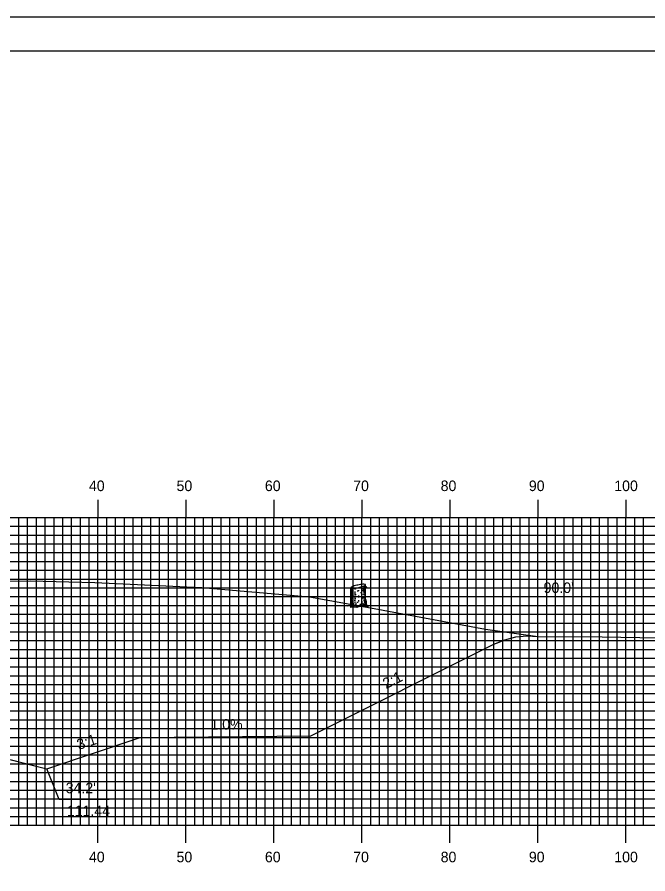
# Model space of a CAD drawing. Extents: x 1767694 to 1768037, y 442591 to 442811.
# Drawn here: x 1767890.3 to 1767961.9, y 442713.1 to 442810.5 of the extents above; entities that cross this region are included whole.
import ezdxf

# ---------------------------------------------------------------- set-up
doc = ezdxf.new("R2010")
doc.units = 0
for name, color, linetype in [('ANNOTATION', 7, 'Continuous'), ('BORDER', 7, 'Continuous'), ('D_Roadway_Centerline', 7, 'Continuous'), ('D_Roadway_SlopeLines', 7, 'Continuous'), ('D_Text_Standard', 7, 'Continuous'), ('H_V ANNOTATION', 7, 'Continuous'), ('M_Trees_Conifer_Pay', 7, 'Continuous'), ('MAJOR', 7, 'Continuous'), ('MINOR', 7, 'Continuous'), ('PLOT BOUNDARY', 7, 'Continuous'), ('S_Roadway_Centerline', 7, 'Continuous')]:
    doc.layers.add(name, color=color, linetype=linetype)

msp = doc.modelspace()

# ---------------------------------------------------------------- linework, layer by layer
at = {"layer": 'ANNOTATION'}
msp.add_lwpolyline([(1767900.736, 442721.591), (1767895.044, 442721.591), (1767893.624, 442725.102)], dxfattribs=at)
at = {"layer": 'BORDER'}
msp.add_lwpolyline([(1767709.85, 442596.665), (1768029.85, 442596.665), (1768029.85, 442806.665), (1767709.85, 442806.665)], close=True, dxfattribs=at)
at = {"layer": 'D_Roadway_Centerline'}
msp.add_lwpolyline([(1767889.623, 442726.102), (1767891.113, 442725.73), (1767893.624, 442725.102), (1767904.248, 442728.644), (1767904.254, 442728.646), (1767904.265, 442728.646), (1767923.635, 442728.839), (1767923.637, 442728.84), (1767944.45, 442739.247), (1767944.845, 442739.413), (1767945.7, 442739.772), (1767946.949, 442740.098), (1767948.2, 442740.223), (1767949.168, 442740.167), (1767949.45, 442740.15)], dxfattribs=at)
at = {"layer": 'D_Roadway_SlopeLines'}
for points in [[(1767904.254, 442728.646), (1767923.635, 442728.839), (1767944.45, 442739.247), (1767945.7, 442739.772), (1767946.949, 442740.098), (1767948.199, 442740.223), (1767949.449, 442740.15)], [(1767879.45, 442728.646), (1767893.624, 442725.102)], [(1767893.624, 442725.102), (1767904.254, 442728.646)]]:
    msp.add_lwpolyline(points, dxfattribs=at)
at = {"layer": 'M_Trees_Conifer_Pay'}
for p, q in [((1767928.198, 442743.956), (1767928.198, 442745.678)), ((1767928.245, 442745.641), (1767928.245, 442745.169)), ((1767928.303, 442745.629), (1767928.303, 442745.532)), ((1767928.303, 442745.457), (1767928.303, 442745.253)), ((1767928.303, 442745.196), (1767928.303, 442744.996)), ((1767928.429, 442745.622), (1767928.429, 442745.389)), ((1767928.429, 442745.349), (1767928.429, 442745.274)), ((1767928.649, 442745.642), (1767928.649, 442745.474)), ((1767928.649, 442745.237), (1767928.649, 442745)), ((1767929.054, 442745.41), (1767929.054, 442745.315)), ((1767929.445, 442745.684), (1767929.445, 442745.484)), ((1767929.445, 442745.427), (1767929.445, 442745.338)), ((1767929.673, 442745.88), (1767929.673, 442745.657)), ((1767929.673, 442745.568), (1767929.673, 442745.521)), ((1767929.673, 442745.186), (1767929.673, 442745.054)), ((1767929.73, 442745.385), (1767929.679, 442745.326)), ((1767929.79, 442745.941), (1767929.79, 442745.778)), ((1767929.79, 442745.711), (1767929.79, 442745.583)), ((1767929.79, 442745.396), (1767929.79, 442745.06)), ((1767929.862, 442744.366), (1767929.862, 442746.013)), ((1767928.245, 442745.105), (1767928.245, 442744.797)), ((1767928.245, 442744.749), (1767928.245, 442744.257)), ((1767928.245, 442744.204), (1767928.245, 442743.956)), ((1767928.303, 442744.949), (1767928.303, 442744.613)), ((1767928.303, 442744.56), (1767928.303, 442744.424)), ((1767928.303, 442744.325), (1767928.303, 442743.946)), ((1767928.429, 442744.871), (1767928.429, 442744.732)), ((1767928.429, 442744.461), (1767928.429, 442744.319)), ((1767928.649, 442744.755), (1767928.649, 442744.603)), ((1767928.649, 442744.56), (1767928.649, 442744.387)), ((1767929.054, 442744.797), (1767929.054, 442744.723)), ((1767929.054, 442744.698), (1767929.054, 442744.549)), ((1767929.054, 442744.257), (1767929.054, 442744.104)), ((1767929.445, 442744.99), (1767929.445, 442744.885)), ((1767929.445, 442744.518), (1767929.445, 442744.372)), ((1767929.673, 442744.943), (1767929.673, 442744.833)), ((1767929.673, 442744.698), (1767929.673, 442744.556)), ((1767929.673, 442744.329), (1767929.673, 442744.156)), ((1767929.79, 442745.023), (1767929.79, 442744.86)), ((1767929.79, 442744.813), (1767929.79, 442744.597)), ((1767929.79, 442744.566), (1767929.79, 442744.492)), ((1767929.79, 442744.451), (1767929.79, 442744.278)), ((1767928.429, 442744.057), (1767928.429, 442743.963)), ((1767928.429, 442743.563), (1767928.592, 442743.627)), ((1767928.649, 442744.109), (1767928.649, 442743.956)), ((1767928.866, 442743.499), (1767928.74, 442743.563)), ((1767929.445, 442744.14), (1767929.445, 442744.051))]:
    msp.add_line(p, q, dxfattribs=at)
for points in [[(1767929.645, 442745.474), (1767929.615, 442745.389), (1767929.611, 442745.322), (1767929.641, 442745.258)], [(1767929.679, 442745.511), (1767929.716, 442745.437), (1767929.763, 442745.494), (1767929.821, 442745.562), (1767929.913, 442745.756), (1767929.977, 442745.803), (1767930.008, 442745.81)], [(1767929.693, 442745.258), (1767929.73, 442745.385), (1767929.794, 442745.501), (1767929.824, 442745.568), (1767929.893, 442745.715)], [(1767929.908, 442745.744), (1767929.983, 442745.752), (1767930.055, 442745.653)], [(1767929.862, 442744.366), (1767929.913, 442744.104), (1767929.929, 442743.831), (1767929.987, 442743.705), (1767930.123, 442743.675), (1767929.893, 442743.637), (1767929.893, 442743.637), (1767929.899, 442743.59), (1767930.146, 442743.496), (1767929.872, 442743.512), (1767929.516, 442743.532), (1767929.195, 442743.522), (1767929.201, 442743.604), (1767929.053, 442743.522), (1767928.866, 442743.499), (1767928.89, 442743.431), (1767928.622, 442743.475), (1767928.402, 442743.448), (1767928.109, 442743.465), (1767928.398, 442743.522), (1767928.429, 442743.563), (1767928.266, 442743.621), (1767928.029, 442743.631), (1767927.788, 442743.631), (1767928.13, 442743.689), (1767928.172, 442743.769), (1767928.198, 442743.956)], [(1767928.377, 442744.984), (1767928.371, 442745.079), (1767928.414, 442745.056), (1767928.414, 442744.961)], [(1767929.516, 442744.585), (1767929.529, 442744.508), (1767929.576, 442744.518), (1767929.563, 442744.685)], [(1767929.788, 442744.224), (1767929.794, 442744.078), (1767929.841, 442744.01), (1767929.851, 442743.81)], [(1767928.246, 442743.909), (1767928.225, 442743.831), (1767928.204, 442743.736)], [(1767928.324, 442743.889), (1767928.33, 442743.773), (1767928.277, 442743.684), (1767928.266, 442743.621)], [(1767928.487, 442743.915), (1767928.487, 442743.784), (1767928.398, 442743.684)], [(1767928.713, 442743.675), (1767928.781, 442743.769), (1767928.807, 442743.909)], [(1767929.201, 442743.604), (1767929.275, 442743.746), (1767929.285, 442743.847)], [(1767929.452, 442743.973), (1767929.462, 442743.847), (1767929.536, 442743.804)], [(1767929.73, 442743.584), (1767929.716, 442743.722), (1767929.641, 442743.851)], [(1767929.689, 442744.078), (1767929.763, 442743.973), (1767929.767, 442743.8), (1767929.893, 442743.637)]]:
    msp.add_lwpolyline(points, dxfattribs=at)
for centre, radius, start, end in [((1767928.23, 442745.5), 0.0334, 163.94846, 180), ((1767928.23, 442745.5), 0.0334, 180, 196.05154), ((1767928.229, 442745.677), 0.0314, 156.51582, 169.2194), ((1767928.224, 442745.678), 0.0264, 169.2194, 180.03145), ((1767928.221, 442745.678), 0.0226, 180.03145, 191.7194), ((1767928.221, 442745.678), 0.0226, 191.7194, 203.40735), ((1767928.24, 442745.503), 0.0441, 196.05154, 210), ((1767928.249, 442745.668), 0.0527, 146.7194, 156.51582), ((1767928.224, 442745.679), 0.0264, 203.40735, 214.2194), ((1767928.228, 442745.682), 0.0314, 214.2194, 226.92298), ((1767928.256, 442745.512), 0.0624, 210, 228.74941), ((1767928.273, 442745.652), 0.0817, 132.38868, 146.7194), ((1767928.243, 442745.698), 0.0527, 226.92298, 236.7194), ((1767928.259, 442745.722), 0.0817, 236.7194, 251.05013), ((1767928.329, 442745.594), 0.172, 228.74941, 240), ((1767928.387, 442745.528), 0.251, 124.2194, 132.38868), ((1767928.314, 442745.881), 0.251, 251.05013, 259.2194), ((1767928.528, 442745.939), 0.571, 240, 240.33672), ((1767928.529, 442745.728), 0.571, 240, 247.05866), ((1767928.697, 442745.072), 0.802, 108.05939, 124.2194), ((1767928.417, 442746.423), 0.802, 259.2194, 275.37941), ((1767928.528, 442745.939), 0.571, 246.85973, 257.98457), ((1767930.054, 442740.91), 5.179, 101.7194, 108.05939), ((1767928.006, 442750.781), 5.179, 275.37941, 281.7194), ((1767929.03, 442749.69), 4.124, 264.6955, 266.73309), ((1767929.029, 442749.457), 4.124, 268.07512, 270), ((1767930.054, 442740.91), 5.179, 95.37941, 101.7194), ((1767929.029, 442749.457), 4.124, 270, 270.35814), ((1767928.006, 442750.781), 5.179, 281.7194, 288.05939), ((1767929.029, 442749.457), 4.124, 275.78493, 277.05584), ((1767929.03, 442749.69), 4.124, 276.23804, 278.1032), ((1767929.643, 442745.268), 0.802, 79.2194, 95.37941), ((1767929.531, 442746.172), 0.571, 278.1032, 284.36665), ((1767929.363, 442746.619), 0.802, 288.05939, 304.2194), ((1767929.531, 442746.327), 0.571, 284.43166, 292.41325), ((1767929.531, 442745.728), 0.571, 284.44928, 297.04285), ((1767929.531, 442746.172), 0.571, 297.0237, 300), ((1767929.746, 442745.81), 0.251, 71.05013, 79.2194), ((1767929.673, 442746.163), 0.251, 304.2194, 312.38868), ((1767929.73, 442745.982), 0.172, 300, 311.25059), ((1767929.73, 442745.827), 0.172, 300, 311.25059), ((1767929.801, 442745.969), 0.0817, 56.7194, 71.05013), ((1767929.787, 442746.039), 0.0817, 312.38868, 326.7194), ((1767929.803, 442745.899), 0.0624, 311.25059, 330), ((1767929.803, 442745.745), 0.0624, 311.25059, 330), ((1767929.817, 442745.994), 0.0527, 46.92298, 56.7194), ((1767929.832, 442746.009), 0.0314, 34.2194, 46.92298), ((1767929.811, 442746.023), 0.0527, 326.7194, 336.51582), ((1767929.818, 442745.89), 0.0441, 330, 343.94846), ((1767929.818, 442745.736), 0.0441, 330, 343.94846), ((1767929.836, 442746.012), 0.0264, 23.40735, 34.2194), ((1767929.831, 442746.014), 0.0314, 336.51582, 349.2194), ((1767929.839, 442746.013), 0.0226, 11.7194, 23.40735), ((1767929.829, 442745.887), 0.0334, 343.94846, 354.21506), ((1767929.829, 442745.733), 0.0334, 343.94846, 354.21506), ((1767929.829, 442745.289), 0.0334, 343.94846, 354.21506), ((1767929.839, 442746.013), 0.0226, 0.03145, 11.7194), ((1767929.836, 442746.013), 0.0264, 349.2194, 0.03145), ((1767928.23, 442745.053), 0.0334, 163.94846, 180), ((1767928.23, 442745.053), 0.0334, 180, 196.05154), ((1767928.23, 442744.843), 0.0334, 163.94846, 180), ((1767928.23, 442744.843), 0.0334, 180, 196.05154), ((1767928.23, 442744.606), 0.0334, 163.94846, 180), ((1767928.23, 442744.606), 0.0334, 180, 196.05154), ((1767928.23, 442744.408), 0.0334, 163.94846, 180), ((1767928.23, 442744.213), 0.0334, 163.94846, 180), ((1767928.23, 442744.213), 0.0334, 180, 196.05154), ((1767928.24, 442745.056), 0.0441, 196.05154, 210), ((1767928.24, 442744.846), 0.0441, 196.05154, 210), ((1767928.24, 442744.609), 0.0441, 196.05154, 210), ((1767928.24, 442744.216), 0.0441, 196.05154, 210), ((1767928.256, 442745.065), 0.0624, 210, 228.74941), ((1767928.256, 442744.855), 0.0624, 210, 228.74941), ((1767928.256, 442744.618), 0.0624, 210, 228.74941), ((1767928.256, 442744.225), 0.0624, 210, 228.74941), ((1767928.329, 442745.148), 0.172, 228.74941, 240), ((1767928.329, 442744.938), 0.172, 228.74941, 240), ((1767928.329, 442744.701), 0.172, 228.74941, 240), ((1767928.528, 442745.493), 0.571, 240, 240.33672), ((1767928.528, 442745.283), 0.571, 240, 246.85973), ((1767928.528, 442745.046), 0.571, 240, 246.85973), ((1767928.517, 442744.854), 0.571, 241.23686, 248.02677), ((1767928.528, 442745.283), 0.571, 259.27072, 261.8968), ((1767929.029, 442748.8), 4.124, 261.8968, 263.14738), ((1767929.029, 442748.366), 4.124, 263.49906, 265.83975), ((1767929.029, 442749.01), 4.124, 264.08098, 266.66759), ((1767929.029, 442748.563), 4.124, 264.71603, 266.31934), ((1767929.029, 442748.8), 4.124, 270, 270.35814), ((1767929.029, 442748.8), 4.124, 273.14934, 275.45691), ((1767929.03, 442749.246), 4.124, 273.70524, 275.95043), ((1767929.029, 442749.01), 4.124, 277.61247, 278.1032), ((1767929.529, 442745.493), 0.571, 278.1032, 286.92962), ((1767929.529, 442745.046), 0.571, 285.39827, 297.18959), ((1767929.529, 442744.848), 0.571, 289.29072, 300), ((1767929.529, 442745.493), 0.571, 297.18959, 300), ((1767929.529, 442745.283), 0.571, 297.18959, 300), ((1767929.729, 442745.148), 0.172, 300, 311.25059), ((1767929.729, 442744.938), 0.172, 300, 311.25059), ((1767929.729, 442744.503), 0.172, 300, 311.25059), ((1767929.801, 442745.065), 0.0624, 311.25059, 330), ((1767929.801, 442744.855), 0.0624, 311.25059, 330), ((1767929.801, 442744.421), 0.0624, 311.25059, 330), ((1767929.817, 442745.056), 0.0441, 330, 343.94846), ((1767929.817, 442744.846), 0.0441, 330, 343.94846), ((1767929.817, 442744.411), 0.0441, 330, 343.94846), ((1767929.827, 442745.053), 0.0334, 343.94846, 354.21506), ((1767929.827, 442744.843), 0.0334, 343.94846, 354.21506), ((1767929.827, 442744.408), 0.0334, 343.94846, 354.21506), ((1767928.23, 442743.993), 0.0334, 163.94846, 180), ((1767928.23, 442743.993), 0.0334, 180, 196.05154), ((1767928.24, 442743.995), 0.0441, 196.05154, 210), ((1767928.256, 442744.005), 0.0624, 210, 228.74941), ((1767928.329, 442744.308), 0.172, 228.74941, 240), ((1767928.329, 442744.087), 0.172, 228.74941, 240), ((1767928.528, 442744.653), 0.571, 240, 246.85973), ((1767928.528, 442744.432), 0.571, 240, 244.53138), ((1767929.029, 442747.95), 4.124, 262.44379, 263.51202), ((1767929.029, 442748.17), 4.124, 267.81166, 270), ((1767929.029, 442748.17), 4.124, 270, 270.13279), ((1767929.029, 442748.17), 4.124, 275.78493, 276.78961), ((1767929.029, 442747.95), 4.124, 277.36842, 278.1032), ((1767929.529, 442744.432), 0.571, 278.1032, 281.63703), ((1767929.529, 442744.653), 0.571, 288.50673, 297.27208), ((1767929.729, 442744.087), 0.172, 300, 311.25059), ((1767929.801, 442744.005), 0.0624, 311.25059, 330), ((1767929.817, 442743.995), 0.0441, 330, 343.94846), ((1767929.827, 442743.993), 0.0334, 343.94846, 354.21506)]:
    msp.add_arc(centre, radius, start, end, dxfattribs=at)
at = {"layer": 'MAJOR'}
for p, q in [((1767899.45, 442755.669), (1767899.45, 442753.665)), ((1767909.45, 442755.669), (1767909.45, 442753.665)), ((1767919.45, 442755.669), (1767919.45, 442753.665)), ((1767929.45, 442755.669), (1767929.45, 442753.665)), ((1767939.45, 442755.669), (1767939.45, 442753.665)), ((1767949.45, 442755.669), (1767949.45, 442753.665)), ((1767959.45, 442755.669), (1767959.45, 442753.665)), ((1767719.45, 442753.665), (1767999.45, 442753.665)), ((1767719.45, 442753.665), (1767999.45, 442753.665)), ((1767899.45, 442718.665), (1767899.45, 442753.665)), ((1767909.45, 442718.665), (1767909.45, 442753.665)), ((1767919.45, 442718.665), (1767919.45, 442753.665)), ((1767929.45, 442718.665), (1767929.45, 442753.665)), ((1767939.45, 442718.665), (1767939.45, 442753.665)), ((1767949.45, 442718.665), (1767949.45, 442753.665)), ((1767959.45, 442718.665), (1767959.45, 442753.665)), ((1767719.45, 442748.665), (1767999.45, 442748.665)), ((1767719.45, 442743.665), (1767999.45, 442743.665)), ((1767719.45, 442738.665), (1767999.45, 442738.665)), ((1767719.45, 442733.665), (1767999.45, 442733.665)), ((1767719.45, 442728.665), (1767999.45, 442728.665)), ((1767719.45, 442723.665), (1767999.45, 442723.665)), ((1767719.45, 442718.665), (1767999.45, 442718.665)), ((1767719.45, 442718.665), (1767999.45, 442718.665)), ((1767899.45, 442716.661), (1767899.45, 442718.665)), ((1767909.45, 442716.661), (1767909.45, 442718.665)), ((1767919.45, 442716.661), (1767919.45, 442718.665)), ((1767929.45, 442716.661), (1767929.45, 442718.665)), ((1767939.45, 442716.661), (1767939.45, 442718.665)), ((1767949.45, 442716.661), (1767949.45, 442718.665)), ((1767959.45, 442716.661), (1767959.45, 442718.665))]:
    msp.add_line(p, q, dxfattribs=at)
at = {"layer": 'MINOR'}
for p, q in [((1767890.45, 442718.665), (1767890.45, 442753.665)), ((1767891.45, 442718.665), (1767891.45, 442753.665)), ((1767892.45, 442718.665), (1767892.45, 442753.665)), ((1767893.45, 442718.665), (1767893.45, 442753.665)), ((1767894.45, 442718.665), (1767894.45, 442753.665)), ((1767895.45, 442718.665), (1767895.45, 442753.665)), ((1767896.45, 442718.665), (1767896.45, 442753.665)), ((1767897.45, 442718.665), (1767897.45, 442753.665)), ((1767898.45, 442718.665), (1767898.45, 442753.665)), ((1767900.45, 442718.665), (1767900.45, 442753.665)), ((1767901.45, 442718.665), (1767901.45, 442753.665)), ((1767902.45, 442718.665), (1767902.45, 442753.665)), ((1767903.45, 442718.665), (1767903.45, 442753.665)), ((1767904.45, 442718.665), (1767904.45, 442753.665)), ((1767905.45, 442718.665), (1767905.45, 442753.665)), ((1767906.45, 442718.665), (1767906.45, 442753.665)), ((1767907.45, 442718.665), (1767907.45, 442753.665)), ((1767908.45, 442718.665), (1767908.45, 442753.665)), ((1767910.45, 442718.665), (1767910.45, 442753.665)), ((1767911.45, 442718.665), (1767911.45, 442753.665)), ((1767912.45, 442718.665), (1767912.45, 442753.665)), ((1767913.45, 442718.665), (1767913.45, 442753.665)), ((1767914.45, 442718.665), (1767914.45, 442753.665)), ((1767915.45, 442718.665), (1767915.45, 442753.665)), ((1767916.45, 442718.665), (1767916.45, 442753.665)), ((1767917.45, 442718.665), (1767917.45, 442753.665)), ((1767918.45, 442718.665), (1767918.45, 442753.665)), ((1767920.45, 442718.665), (1767920.45, 442753.665)), ((1767921.45, 442718.665), (1767921.45, 442753.665)), ((1767922.45, 442718.665), (1767922.45, 442753.665)), ((1767923.45, 442718.665), (1767923.45, 442753.665)), ((1767924.45, 442718.665), (1767924.45, 442753.665)), ((1767925.45, 442718.665), (1767925.45, 442753.665)), ((1767926.45, 442718.665), (1767926.45, 442753.665)), ((1767927.45, 442718.665), (1767927.45, 442753.665)), ((1767928.45, 442718.665), (1767928.45, 442753.665)), ((1767930.45, 442718.665), (1767930.45, 442753.665)), ((1767931.45, 442718.665), (1767931.45, 442753.665)), ((1767932.45, 442718.665), (1767932.45, 442753.665)), ((1767933.45, 442718.665), (1767933.45, 442753.665)), ((1767934.45, 442718.665), (1767934.45, 442753.665)), ((1767935.45, 442718.665), (1767935.45, 442753.665)), ((1767936.45, 442718.665), (1767936.45, 442753.665)), ((1767937.45, 442718.665), (1767937.45, 442753.665)), ((1767938.45, 442718.665), (1767938.45, 442753.665)), ((1767940.45, 442718.665), (1767940.45, 442753.665)), ((1767941.45, 442718.665), (1767941.45, 442753.665)), ((1767942.45, 442718.665), (1767942.45, 442753.665)), ((1767943.45, 442718.665), (1767943.45, 442753.665)), ((1767944.45, 442718.665), (1767944.45, 442753.665)), ((1767945.45, 442718.665), (1767945.45, 442753.665)), ((1767946.45, 442718.665), (1767946.45, 442753.665)), ((1767947.45, 442718.665), (1767947.45, 442753.665)), ((1767948.45, 442718.665), (1767948.45, 442753.665)), ((1767950.45, 442718.665), (1767950.45, 442753.665)), ((1767951.45, 442718.665), (1767951.45, 442753.665)), ((1767952.45, 442718.665), (1767952.45, 442753.665)), ((1767953.45, 442718.665), (1767953.45, 442753.665)), ((1767954.45, 442718.665), (1767954.45, 442753.665)), ((1767955.45, 442718.665), (1767955.45, 442753.665)), ((1767956.45, 442718.665), (1767956.45, 442753.665)), ((1767957.45, 442718.665), (1767957.45, 442753.665)), ((1767958.45, 442718.665), (1767958.45, 442753.665)), ((1767960.45, 442718.665), (1767960.45, 442753.665)), ((1767961.45, 442718.665), (1767961.45, 442753.665)), ((1767719.45, 442752.665), (1767999.45, 442752.665)), ((1767719.45, 442751.665), (1767999.45, 442751.665)), ((1767719.45, 442750.665), (1767999.45, 442750.665)), ((1767719.45, 442749.665), (1767999.45, 442749.665)), ((1767719.45, 442747.665), (1767999.45, 442747.665)), ((1767719.45, 442746.665), (1767999.45, 442746.665)), ((1767719.45, 442745.665), (1767999.45, 442745.665)), ((1767719.45, 442744.665), (1767999.45, 442744.665)), ((1767719.45, 442742.665), (1767999.45, 442742.665)), ((1767719.45, 442741.665), (1767999.45, 442741.665)), ((1767719.45, 442740.665), (1767999.45, 442740.665)), ((1767719.45, 442739.665), (1767999.45, 442739.665)), ((1767719.45, 442737.665), (1767999.45, 442737.665)), ((1767719.45, 442736.665), (1767999.45, 442736.665)), ((1767719.45, 442735.665), (1767999.45, 442735.665)), ((1767719.45, 442734.665), (1767999.45, 442734.665)), ((1767719.45, 442732.665), (1767999.45, 442732.665)), ((1767719.45, 442731.665), (1767999.45, 442731.665)), ((1767719.45, 442730.665), (1767999.45, 442730.665)), ((1767719.45, 442729.665), (1767999.45, 442729.665)), ((1767719.45, 442727.665), (1767999.45, 442727.665)), ((1767719.45, 442726.665), (1767999.45, 442726.665)), ((1767719.45, 442725.665), (1767999.45, 442725.665)), ((1767719.45, 442724.665), (1767999.45, 442724.665)), ((1767719.45, 442722.665), (1767999.45, 442722.665)), ((1767719.45, 442721.665), (1767999.45, 442721.665)), ((1767719.45, 442720.665), (1767999.45, 442720.665)), ((1767719.45, 442719.665), (1767999.45, 442719.665))]:
    msp.add_line(p, q, dxfattribs=at)
at = {"layer": 'PLOT BOUNDARY'}
msp.add_lwpolyline([(1767693.663, 442590.547), (1768033.663, 442590.547), (1768033.663, 442810.547), (1767693.663, 442810.547)], close=True, dxfattribs=at)
at = {"layer": 'S_Roadway_Centerline'}
msp.add_lwpolyline([(1767875.146, 442746.389), (1767891.751, 442746.451), (1767899.097, 442746.279), (1767911.166, 442745.693), (1767911.198, 442745.692), (1767911.252, 442745.687), (1767923.487, 442744.636), (1767930.858, 442743.315), (1767943.489, 442740.979), (1767949.442, 442740.15), (1767956.744, 442740.109), (1767967.425, 442739.897), (1767975.094, 442739.517), (1767982.566, 442739.022), (1767987.71, 442738.935), (1767999.45, 442738.58)], dxfattribs=at)

# ---------------------------------------------------------------- texts
at = {"layer": 'ANNOTATION'}
for s, rotation, p in [('2:1', 26.56664, (1767932.189, 442734.152)), ('1.0%', 0.57055, (1767912.239, 442729.526)), ('3:1', 18.43781, (1767897.275, 442727.228))]:
    msp.add_text(s, height=1.2, rotation=rotation, dxfattribs=at).set_placement(p)
for s, p in [("34.2'", (1767895.779, 442722.317)), ('111.44', (1767895.913, 442719.717))]:
    msp.add_text(s, height=1.2, dxfattribs=at).set_placement(p)
at = {"layer": 'D_Text_Standard'}
msp.add_text("90.0'", height=1.2, dxfattribs=at).set_placement((1767950.101, 442745.079))
at = {"layer": 'H_V ANNOTATION'}
for s, p in [('40', (1767898.422, 442756.665)), ('50', (1767908.379, 442756.665)), ('60', (1767918.422, 442756.665)), ('70', (1767928.454, 442756.665)), ('80', (1767938.4, 442756.665)), ('90', (1767948.422, 442756.665)), ('100', (1767958.133, 442756.665)), ('40', (1767898.422, 442714.465)), ('50', (1767908.379, 442714.465)), ('60', (1767918.422, 442714.465)), ('70', (1767928.454, 442714.465)), ('80', (1767938.4, 442714.465)), ('90', (1767948.422, 442714.465)), ('100', (1767958.133, 442714.465))]:
    msp.add_text(s, height=1.2, dxfattribs=at).set_placement(p)

doc.saveas('drawing.dxf')
